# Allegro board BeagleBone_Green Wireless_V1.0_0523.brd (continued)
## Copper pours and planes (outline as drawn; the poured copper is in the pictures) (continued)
DGND on BOTTOM: 24.13,97.21 27.79,97.21 28.14,96.85 28.14,95.05 27.89,94.79 27.89,93.09 27.38,92.58 24.59,92.58 23.99,93.18 23.99,95.08 23.47,95.61 23.47,96.55
DGND on BOTTOM: 7.39,111.86 4.6,111.86 4.45,112.01 4.45,112.7 5.28,113.54 5.28,114.88 5.54,115.14 7.16,115.14 7.57,114.73 7.57,112.04
DGND on BOTTOM: 60.35,111.35 63.58,111.35 63.7,111.23 63.7,110.11 62.56,108.97 62.56,108.69 62.59,108.66 62.59,108.64 62.43,108.48 61.7,108.48 61.59,108.59 61.59,108.97 60.1,110.46 60.1,111.1
DGND on BOTTOM: 8.92,95.94 10.29,95.94 10.92,95.3 14.86,95.3 15.19,94.97 15.19,93.55 14.76,93.12 9.02,93.12 8.41,93.73 8.41,95.43
DGND on BOTTOM: 43.33,95.71 43.56,95.48 43.56,94.84 43.31,94.59 43.31,94.21 42.67,94.21 42.67,94.26 42.52,94.41 42.52,94.46 42.29,94.69 42.29,94.72 42.09,94.92 41.68,94.92 41.66,94.95 41.66,95.48 41.91,95.73 41.91,96.39 42.09,96.57 42.09,96.93 42.19,97.03 42.62,97.03 42.72,97.13 42.72,97.89 42.77,97.94 43.21,97.94 43.33,97.82
DGND on BOTTOM: 20.95,81.19 20.95,80.87 21.29,80.54 22.05,80.54 22.35,80.24 22.35,78.51 22.48,78.38 22.48,78.33 23.94,78.33 24.51,78.91 25.53,78.91 25.78,79.16 25.78,79.79 26.54,79.79 26.54,79.54 26.8,79.29 27.43,79.29 27.69,79.54 27.69,81.71 27.66,81.74 27.66,81.79 27.18,82.27 27.18,82.91 27.05,83.03 26.67,83.03 26.16,82.52 26.16,82.02 26.04,81.89 24.87,81.89 24.64,81.66 24.64,80.94 23.88,80.94 23.88,81.66 23.67,81.86 22.86,81.86 22.73,81.74 22.73,80.94 21.97,80.94 21.97,81.58 21.77,81.79 21.03,81.79 20.95,81.71 20.95,81.56 20.96,81.55 20.96,81.2
DGND on BOTTOM: 10.34,109.63 11.07,109.63 11.35,109.35 11.89,109.35 12.37,109.83 12.37,110.26 13.03,110.92 13.06,110.92 13.21,111.07 13.21,111.91 13.31,112.01 14.33,112.01 15.34,111 15.34,107.82 14.66,107.14 10.49,107.14 10.34,107.29
DGND on BOTTOM: 9.09,82.02 8.97,81.89 8.43,81.89 8.28,82.04 7.95,82.04 7.7,82.3 7.7,83.69 7.85,83.85 8.66,83.85 9.09,83.41
DGND on BOTTOM: 8.33,92.3 16.1,92.3 16.87,91.54 16.87,85.14 15.82,84.1 14.1,84.1 13.74,84.46 13.74,86.89 14.02,87.17 14.02,89.03 13.64,89.41 10.06,89.41 10.01,89.36 8.31,89.36 7.67,89.99 7.67,91.64
DGND on BOTTOM: outline of 210 points within 53.09,73.41 87.07,118.21
DGND on BOTTOM: 21.29,105.97 20.22,105.97 20.12,106.07 20.12,108.46 20.14,108.48 19.41,109.22 19.41,109.98 19.81,110.39 22.99,110.39 24.03,109.35 24.03,105.94 23.42,105.33 23.42,104.9 22.4,103.89 22.4,98.91 20.9,97.41 19.86,97.41 19.41,97.87 19.41,100.71 19.58,100.89 21.31,100.89 21.44,101.02 21.44,101.63 21.01,102.06 21.01,102.36 21.13,102.49 21.84,102.49 21.89,102.54 21.89,104.5 22.61,105.21 22.61,106.81 22.38,107.04 21.59,107.04 21.34,106.78 21.34,106.02
DGND on BOTTOM: 2.87,105.74 9.8,105.74 10.52,105.03 10.52,103.45 8.71,101.65 5.77,101.65 4.55,100.43 4.55,84.3 4.29,84.05 4.29,83.59 4.32,83.57 4.32,78.61 4.9,78.03 7.01,78.03 7.14,77.9 7.14,77.55 6.96,77.37 4.14,77.37 4.11,77.39 3.51,77.39 3.1,76.99 3.1,74.22 3.68,73.63 4.34,73.63 4.39,73.69 8.25,73.69 8.79,74.22 8.79,77.06 9.02,77.29 9.88,77.29 10.97,76.2 15.24,76.2 16.08,75.36 16.08,73.13 16.15,73.05 16.15,71.73 15.14,70.71 4.17,70.71 2.54,72.34 2.54,105.41
DGND on BOTTOM: 32.26,95.81 34.67,95.81 35.56,94.92 35.99,94.92 36.12,94.79 36.12,94.26 35.86,94.01 33.43,94.01 32.97,93.55 32.97,91.03 32.74,90.81 31.7,90.81 31.29,91.21 31.29,94.84
DGND on LYR2_GND: 87.12,77.83 83.59,69.29 75.06,65.76 7.75,65.76 3.71,67.43 2.03,71.48 2.03,113.39 3.71,117.43 7.75,119.1 75.06,119.1 75.22,119.1 75.39,119.1 78.13,118.62 81.36,117.3 81.92,116.71 81.92,116.43 85.69,112.66 87.1,107.52 87.12,107.16
DGND on LYR3: 78.82,103.63 75.34,107.11 74.4,107.11 72.82,108.69 72.82,116.36 74.55,118.08 81.28,118.08 85.6,113.77 85.6,112.9 85.98,112.52 85.98,109.98 85.73,109.73 85.14,109.73 83.13,107.72 83.13,105.38 81.38,103.63 ; 1 cut-out
DGND on LYR3: 46.52,101.82 46.74,101.6 47.24,101.6 47.37,101.73 47.37,106.27 46.86,106.78 46.86,108.92 46.2,109.58 45.39,109.58 45.06,109.25 45.06,106.53 46.38,105.21 46.38,104.04 45.82,103.48 45.82,102.29 46.29,101.82
DGND on LYR3: 68.07,100.99 71.6,97.46 71.6,85.83 70.59,84.81 70.59,83.54 70.36,83.31 69.75,83.31 69.55,83.52 69.29,83.52 69.04,83.26 69.04,81.61 68,80.57 56.97,80.57 56.39,81.15 56.39,81.99 56.52,82.12 57,82.12 57.61,81.51 57.61,81.41 57.96,81.05 66.17,81.05 67.95,82.83 67.95,95.35 63.55,99.75 57.96,99.75 57.61,100.1 57.61,100.33 57.81,100.53 58.39,100.53 58.85,100.99
DGND on LYR3: 3.53,105.64 16.23,105.64 17.07,104.8 17.07,103.12 15.9,101.96 11.58,101.96 10.79,101.17 10.79,95.61 11.76,94.64 15.42,94.64 16.66,93.4 16.66,88.44 17.4,87.71 17.4,84.58 16.28,83.46 11.48,83.46 10.93,82.92 10.93,77.3 11.43,76.81 15.72,76.81 16.15,76.38 16.15,74.78 15.85,74.47 13.31,74.47 12.56,73.72 12.56,71.23 12.14,70.82 4.67,70.82 3,72.49 3,105.08 3.53,105.61
DGND on LYR3: 26.42,84.68 27.81,83.29 27.81,82.91 28.83,81.89 28.83,80.37 27.1,78.64 27.1,77.22 25.91,76.02 25.4,76.02 25.15,76.28 25.15,76.5 24.38,77.27 24,77.27 23.94,77.2 22.59,77.2 19.25,80.54 19.25,82.5 19.79,83.03 22.86,83.03 23.88,84.05 23.88,84.18 24.38,84.68
DGND on LYR4: 77.42,103.78 72.39,108.81 69.19,108.81 68.58,108.2 62.99,108.2 61.52,109.68 61.52,111.63 58.83,114.33 58.83,116.84 59.05,117.07 77.6,117.07 78.49,117.96 79.81,117.96 81.23,117.27 82.37,116.54 85.12,113.51 85.93,112.19 85.93,109.98 83.36,107.42 83.36,105.36 81.79,103.78
DGND on LYR5_PWR: 32.26,73 39.62,73 40.77,71.86 40.77,69.95 41.02,69.7 61.98,69.7 62.61,70.33 62.61,80.85 62.94,81.18 67.61,81.18 68.94,82.5 68.94,83.06 69.44,83.57 69.44,95.96 68.45,96.95 68.25,96.95 64.77,100.43 61.47,100.43 61.01,99.97 56.46,99.97 55.96,100.48 55.96,105.59 55.42,106.12 54.84,106.12 52.6,108.36 51.31,108.36 49.38,110.29 48.36,110.29 48.01,110.64 48.01,118.14 48.44,118.57 77.72,118.57 77.72,118.21 78.49,117.45 78.74,117.45 78.8,117.51 80.45,117.51 85.6,112.37 85.6,109.22 85.57,109.19 85.57,104.19 85.29,103.91 85.29,93.65 86,92.94 86,85.95 85.62,85.57 85.62,76.56 84.1,75.03 79.83,75.03 78.44,73.63 78.44,67.87 76.96,66.4 25.27,66.4 24.89,66.78 24.89,70.33 25.91,71.35 30.61,71.35
GND_EARTH on TOP: 80.9,74.85 81.74,74.85 86.56,79.68 86.56,94.92 85.67,95.81 85.67,102.24 86.03,102.59 86.72,102.59 87.05,102.26 87.05,76.78 86.82,76.56 86.82,75.46 86.74,75.39 82.76,68.55 75.34,65.84 75.29,65.79 7.77,65.79 3.78,67.38 2.06,71.32 2.06,113.51 4.11,117.64 8.48,119.08 18.8,119.08 19.15,118.72 19.15,115.87 17.68,114.4 13.72,114.4 12.37,115.75 8.61,115.75 7.87,116.48 4.93,116.48 4.83,116.38 4.83,113.39 3.38,111.94 3.38,109.27 3.53,109.12 3.89,109.12 4.85,108.15 4.85,106.27 4.62,106.05 3.58,106.05 2.63,105.09 2.63,71.77 4.19,70.21 15.39,70.21 15.75,70.56 21.87,70.56 22.53,69.9 22.53,67.01 23.29,66.24 29.64,66.24 30.05,66.65 69.72,66.65 72.57,69.49 72.57,70.48 72.76,70.68 77.43,70.68 78.97,72.21 78.97,72.92
GND_EARTH on BOTTOM: 79.3,74.85 81.74,74.85 86.56,79.68 86.56,79.71 86.59,79.68 87.05,79.68 87.05,76.78 86.82,76.56 86.82,75.46 86.74,75.39 82.76,68.55 75.34,65.84 75.29,65.79 7.77,65.79 3.78,67.38 2.06,71.32 2.06,113.51 4.11,117.64 8.48,119.08 18.8,119.08 19.15,118.72 19.15,115.87 17.68,114.4 13.72,114.4 12.37,115.75 8.1,115.75 7.04,114.68 7.04,113.54 6.73,113.23 4.67,113.23 4.32,112.88 4.32,108.94 5.03,108.23 6.55,108.23 6.73,108.05 6.73,106.38 6.4,106.05 2.74,106.05 2.34,105.64 2.34,72.06 4.19,70.21 15.39,70.21 17.27,72.09 18.52,72.09 20.04,70.56 21.87,70.56 22.53,69.9 22.53,67.01 23.29,66.24 26.67,66.24 26.82,66.09 30.05,66.09 30.61,66.65 69.72,66.65 72.57,69.49 72.57,70.48 73.03,70.94 77.29,70.94 78.41,72.06 78.41,73.96
GND_EARTH on LYR3: 79.3,74.85 81.74,74.85 86.56,79.68 86.56,93.9 86.5,93.97 86.5,95.71 85.78,96.43 85.78,105.41 86.18,105.82 86.18,107.16 86.13,107.21 86.13,109.3 86.26,109.42 86.54,109.42 86.82,109.14 86.82,107.31 87.1,107.04 87.1,94.89 87.05,94.84 87.05,76.78 86.82,76.56 86.82,75.46 86.74,75.39 82.76,68.55 75.34,65.84 75.29,65.79 7.77,65.79 3.78,67.38 2.06,71.32 2.06,113.51 4.11,117.64 8.48,119.08 18.8,119.08 19.15,118.72 19.15,115.87 17.68,114.4 13.72,114.4 12.37,115.75 8.1,115.75 8.09,115.74 5.88,115.74 5.18,115.04 5.18,113.74 4.32,112.88 4.32,108.94 5.03,108.23 5.08,108.23 5.05,108.2 5.05,106.48 4.62,106.05 2.74,106.05 2.34,105.64 2.34,72.06 4.19,70.21 15.39,70.21 16.14,70.95 18.1,70.95 19.23,69.82 19.23,67.26 20.24,66.24 29.64,66.24 30.05,66.65 69.72,66.65 72.57,69.49 72.57,70.48 73.03,70.94 77.29,70.94 78.41,72.06 78.41,73.96
GND_EARTH on LYR4: 79.3,74.85 81.74,74.85 86.56,79.68 86.56,95.45 86.22,95.8 86.09,95.8 85.57,96.32 85.57,100.23 85.93,100.58 85.93,109.12 86.13,109.32 86.54,109.32 86.79,109.07 86.79,107.98 87.05,107.72 87.05,76.78 86.82,76.56 86.82,75.46 86.74,75.39 82.76,68.55 75.34,65.84 75.29,65.79 7.77,65.79 3.78,67.38 2.06,71.32 2.06,113.51 4.11,117.64 8.48,119.08 18.8,119.08 19.15,118.72 19.15,115.87 17.68,114.4 13.72,114.4 12.37,115.75 8.1,115.75 7.04,114.68 7.04,113.54 6.73,113.23 4.67,113.23 4.32,112.88 4.32,107.11 3.76,106.55 3.76,106.35 2.79,105.38 2.79,72.82 5.41,70.21 15.39,70.21 15.77,70.59 17.14,70.59 19.81,67.92 20.93,67.92 21.59,67.26 22.53,67.26 22.53,67.01 23.29,66.24 29.64,66.24 30.05,66.65 69.72,66.65 72.57,69.49 72.57,70.48 73.03,70.94 77.29,70.94 78.41,72.06 78.41,73.96
GND_OSC0 on BOTTOM: 39.42,103.91 39.22,104.11 36.02,104.11 35.89,104.24 35.89,110.24 35.81,110.31 35.99,110.49 41.2,110.49 41.68,110.01 41.68,109.93 42.8,108.81 43.08,108.81 43.1,108.79 44.04,108.79 44.45,109.19 46.43,109.19 47.6,108.03 47.6,105.51 46.23,104.14 44.55,104.14 43.9,104.79 43.9,105.42 43.71,105.61 41.78,105.61 41.2,105.03 40.69,105.03 40.46,104.8 40.46,104.42 39.95,103.91 ; 1 cut-out
GND_OSC1 on TOP: 49.66,75.29 49.91,75.03 55.12,75.03 55.37,75.29 55.37,82.91 54.48,83.79 53.72,83.79 52.45,85.06 52.45,86.97 51.56,87.86 50.29,87.86 50.16,87.73 50.16,85.32 49.53,84.68 49.53,83.79 49.66,83.67
VDD_1V8 on TOP: 26.07,84.47 25.6,84.94 25.6,85.09 26.57,86.06 27.64,86.06 28.17,86.59 28.17,87.73 28.3,87.86 28.5,87.86 28.52,87.83 28.68,87.99 29.11,87.99 30.28,89.15 30.81,89.15 30.84,89.18 31.11,89.18 31.34,88.95 31.34,88.42 29.9,86.97 29.9,85.67 29.08,84.86 26.92,84.86 26.53,84.47
VDD_1V8 on BOTTOM: 38.48,98.86 38.53,98.91 38.53,98.96 38.81,99.24 39.19,99.24 39.37,99.06 39.37,98.4 39.8,97.97 41.58,97.97 41.81,97.74 41.81,97.54 41.55,97.28 40.46,97.28 40.41,97.33 37.46,97.33 37.26,97.13 36.17,97.13 35.81,96.77 35.81,95.89 35.71,95.78 34.98,95.78 34.51,96.25 34.51,96.84 34.49,96.85 34.49,97.82 34.82,98.15 35.51,98.15 36.22,98.86
VDD_1V8 on LYR3: 41.68,97.38 37.54,97.38 37.39,97.54 37.39,98.5 37.77,98.88 38.2,98.88 38.73,99.42 40.08,99.42 40.34,99.67 41.4,99.67 41.81,99.26 41.81,97.51
VDD_1V8 on LYR4: 31.29,88.19 31.7,88.6 31.7,90.53 33.2,92.02 34.09,92.02 34.52,92.46 34.52,93.85 36.27,95.61 36.27,96.98 36.08,97.17 34.73,97.17 34.57,97 34.57,95.07 33.2,93.7 31.37,93.7 30.63,92.96 30.63,90.65 30.05,90.07 30.05,88.34 30.2,88.19
VDD_1V8 on LYR4: 47.12,90.27 46.86,90.02 43.05,90.02 42.8,90.27 42.8,93.57 42.55,93.83 41.4,93.83 41.15,94.08 41.15,99.42 41.4,99.67 43.94,99.67 44.2,99.92 44.2,100.38 44.58,100.76 46.53,100.76 47.12,100.18 47.12,94.84 46.74,94.46 46.74,94.21 47.12,93.83
VDD_1V8 on LYR5_PWR: 46.1,79.1 46.1,90.4 46.23,90.53 48.13,90.53 48.26,90.4 48.26,85.57 48.64,85.19 50.29,85.19 50.55,84.94 50.55,79.1 50.29,78.84 46.35,78.84
VDD_1V8_WIFI on BOTTOM: 73,88.6 74.37,88.6 74.7,88.93 74.7,89.64 74.68,89.66 74.68,90.09 74.19,90.58 74.19,97.92 73.41,98.7 72.31,98.7 71.65,99.36 71.65,101.6 72.54,102.49 72.54,103.33 72.31,103.56 70.51,103.56 70.23,103.28 70.23,102.57 70.59,102.21 70.71,102.21 70.97,101.96 70.97,101.19 70.61,100.84 70.61,99.31 72.54,97.38 72.54,95.91 72.8,95.66 72.8,88.8
VDD_3V3_WIFI on TOP: 63.04,113.87 64.06,113.87 64.24,113.69 64.24,112.19 64.08,112.04 63.07,112.04 62.99,112.12 62.99,113.61 62.92,113.69 62.92,113.74
VDD_3V3_WIFI on BOTTOM: 56.77,108.94 56.9,109.07 56.9,110.03 59.06,112.2 59.06,113.73 59.25,113.92 64.24,113.92 64.44,113.72 64.44,113.08 63.25,111.89 60.22,111.89 59.49,111.15 59.49,110.34 60.02,109.8 60.58,109.8 60.99,109.4 60.99,108.86 60.39,108.27 54.9,108.27 54.05,107.42 53.7,107.42 53.44,107.67 53.44,108.15 54.23,108.94
VDD_3V3_WIFI on LYR4: 57.81,110.46 60.32,110.46 61.19,109.6 61.19,109.09 60.66,108.56 60.35,108.56 60.22,108.43 60.22,107.57 61.09,106.71 62.61,106.71 63.37,105.94 63.37,105.41 62.51,104.55 61.29,104.55 57.58,108.25 57.58,110.24
VDD_3V3A on BOTTOM: 39.98,96.39 41.63,96.39 41.81,96.57 41.81,96.93 42.04,97.16 42.44,97.16 42.57,97.28 42.57,97.66 42.42,97.82 42.19,97.82 41.76,97.38 41.76,97.31 41.63,97.18 41.48,97.18 41.4,97.1 39.98,97.1 39.85,96.98 39.85,96.52
VDD_3V3A on BOTTOM: 42.16,94.36 42.16,94.21 42.42,93.95 43.05,93.95 43.31,93.7 43.31,92.68 42.8,92.68 42.8,93.07 42.42,93.45 41.91,93.45 41.66,93.7 40.49,93.7 40.11,94.08 40.11,95.07 40.18,95.15 41.17,95.15 41.25,95.07 41.25,94.77 41.45,94.56 41.96,94.56
VDD_3V3A on BOTTOM: 43.69,101.57 43.69,100.94 43.31,100.56 43.31,98.4 43.56,98.15 44.7,98.15 44.83,98.27 44.83,98.4 44.45,98.78 44.45,100.69 44.16,100.98 44.16,101.57
VDD_3V3A on BOTTOM: 49.53,98.15 51.43,98.15 51.69,98.4 51.69,100.3 52.15,100.77 52.15,101.57 51.95,101.78 50.04,101.78 49.89,101.63 49.89,100.79 49.66,100.56 49.66,98.78 49.4,98.53 49.4,98.27
VDD_3V3A on LYR5_PWR: 22.99,76.81 22.73,77.06 22.73,89.13 24.51,90.91 25.27,90.91 29.84,95.48 29.84,102.34 30.86,103.35 34.8,103.35 35.86,104.42 35.86,110.06 36.22,110.41 42.27,110.41 42.85,109.83 49.35,109.83 51.23,107.95 52.53,107.95 54.58,105.89 55.07,105.89 55.65,105.31 55.65,100.36 55.24,99.95 55.24,99.92 54.99,99.67 51.94,99.67 51.56,99.29 51.56,96.62 50.55,95.61 50.55,94.59 50.29,94.34 43.94,94.34 43.43,93.83 43.43,93.45 43.31,93.32 42.04,93.32 41.78,93.07 41.78,92.43 42.04,92.18 43.31,92.18 43.56,91.92 43.56,91.67 42.55,90.65 42.55,90.02 42.8,89.76 44.2,89.76 44.45,90.02 44.45,90.4 44.58,90.53 45.72,90.53 45.85,90.4 45.85,78.97 46.23,78.59 50.29,78.59 50.55,78.33 50.55,70.71 50.29,70.46 41.27,70.46 41.02,70.71 41.02,76.43 40.64,76.81
VDD_3V3B on BOTTOM: 19.43,107.29 17.37,107.29 17.25,107.16 17.25,104.22 17.48,103.99 20.7,103.99 21.21,104.5 21.21,105.38 20.83,105.77 19.68,105.77 19.56,105.89 19.56,107.16
VDD_3V3B on BOTTOM: 58.6,111.89 57.68,111.89 57.15,112.42 57.15,114.05 57.48,114.38 58.42,114.38 58.7,114.1 58.7,111.99
VDD_3V3B on LYR5_PWR: 20.13,66.4 19.49,67.03 19.49,69.57 17.91,71.16 14.1,71.16 11.56,68.62 5.21,68.62 3.3,70.52 3.3,113.39 4.6,116.53 7.75,117.83 12.19,117.83 12.51,117.51 12.51,115.29 14.1,113.7 17.91,113.7 19.49,115.29 19.49,117.83 20.13,118.47 60.48,118.47 85.65,93.29 85.65,82.25 84.33,80.92 77.6,80.92 75.74,82.78 75.74,94.11 59.77,110.08 43.1,110.08 42.52,110.67 36.09,110.67 35.64,110.21 35.64,104.57 34.8,103.73 30.73,103.73 29.46,102.46 29.46,95.73 25.02,91.29 24.13,91.29 22.48,89.64 22.48,76.94 22.86,76.56 40.45,76.56 40.77,76.24 40.77,70.84 40.45,70.52 27.43,70.52 27.11,70.21 27.11,66.71 26.8,66.4
VDD_5V on TOP: 20.66,78.86 20.66,79.07 18.67,79.07 17.98,78.38 17.98,76.84 18.14,76.68 19.07,76.68 19.75,77.37 19.75,78.11 20.51,78.86
VDD_5V on BOTTOM: 18.06,78.77 19.13,78.77 19.33,78.56 20.17,78.56 20.7,78.03 20.7,77.17 20.22,76.68 18.16,76.68 17.91,76.94 17.91,77.42 17.93,77.44 17.93,78.64
VDD_5V on LYR4: 19.71,78.46 20.09,78.08 20.09,73.94 20.69,73.34 22.9,73.34 24.43,71.81 25.96,71.81 27.14,70.62 27.14,66.51 27.05,66.42 25.37,66.42 24.59,67.21 24.59,67.23 24.16,67.23 23.14,68.25 20.73,68.25 20.6,68.38 20.57,68.38 16.97,71.98 16.97,77.88 17.55,78.46
VDD_CORE on TOP: 28.7,79.22 28.7,78.08 28.96,77.83 32.03,77.83 32.04,77.84 33.19,77.84 33.5,78.16 33.5,84.15 33.1,84.56 33.1,85.92 34.47,87.29 34.47,88.27 34.44,88.29 34.44,88.49 37.33,91.38 37.33,93.14 35.81,94.65 34.25,94.65 33.81,94.21 33.81,91.49 31.61,89.29 31.61,88.56 30.23,87.17 30.23,83.34 31.09,82.47 31.09,80.59 30.48,79.98 28,79.98 27.88,79.87 27.3,79.87 27.3,79.67 28.26,79.67
VDD_CORE on BOTTOM: 37.29,92.74 37.29,90.53 35.89,89.13 34.29,89.13 33.78,89.64 33.4,89.64 33.27,89.76 33.27,93.45 33.53,93.7 35.79,93.7 36.55,92.94 37.08,92.94
VDD_CORE on LYR3: 50.55,90.65 47.37,90.65 47.12,90.91 47.12,92.05 46.74,92.43 43.81,92.43 43.56,92.18 43.56,89.26 43.31,89 34.16,89 33.4,89.76 33.4,93.12 36.68,96.39 40.46,96.39 40.69,96.62 42.8,96.62 43.18,97 44.83,97 46.61,98.78 50.55,98.78 50.8,98.53 50.8,90.91
VDD_CORE on LYR4: 33.15,91.41 34.52,91.41 34.87,91.06 34.87,89.38 34.01,88.52 34.01,86.49 33.25,85.73 33.25,78.59 32.79,78.13 31.37,78.13 30.71,78.79 30.71,83.44 30.28,83.87 30.28,86.69 32.11,88.52 32.11,90.37
VDD_MPU on TOP: 26.61,76.87 26.42,76.87 26.42,77.51 27.11,77.51 27.94,76.68 30.23,76.68 30.86,76.05 30.86,73.25 30.48,72.87 29.34,72.87 29.08,73.13 29.08,74.27 28.57,74.78 27.74,74.78 27.3,75.21 27.3,76.17
VDD_MPU on TOP: 36.73,87.73 37.69,87.73 37.92,87.5 37.92,86.56 37.59,86.23 36.68,86.23 36.45,86.46 36.45,87.45
VDD_MPU on BOTTOM: 27.48,75.44 28.6,75.44 28.85,75.18 28.85,72.97 28.65,72.77 27.58,72.77 27.36,73 27.36,75.31
VDD_MPU on LYR3: 46.86,86.21 46.86,91.92 46.61,92.18 43.94,92.18 43.81,92.05 43.81,88.75 42.67,87.6 37.34,87.6 37.21,87.48 37.21,86.46 37.34,86.33 41.53,86.33 41.91,85.95 46.61,85.95
VDD_PLL on BOTTOM: 44.96,98.65 45.47,98.15 45.59,98.15 46.48,99.03 46.48,99.29 46.1,99.67 46.1,100.56 45.37,101.29 45.37,101.57 44.86,101.57 44.86,100.91 44.96,100.81
VDD_PLL on BOTTOM: 49.91,85.19 49.91,87.86 50.16,88.11 50.16,90.27 49.91,90.53 49.15,90.53 48.89,90.27 48.89,86.33 49.4,85.83 49.4,85.19
VDD_PLL on BOTTOM: 38,97.21 38.48,97.21 38.63,97.05 38.63,96.67 37.82,95.86 37.82,95.43 37.64,95.25 37.64,94.03 38.23,93.45 41.35,93.45 41.63,93.17 42.37,93.17 42.55,92.99 42.55,92.53 42.32,92.3 41.61,92.3 41.45,92.46 38.02,92.46 36.33,94.15 36.33,95.26 36.17,95.43 36.17,96.6 36.25,96.67 37.74,96.67 37.92,96.85 37.92,97.13
VDD_PLL on LYR5_PWR: 42.04,92.56 42.16,92.43 43.81,92.43 44.07,92.68 47.75,92.68 48.51,91.92 48.51,90.27 48.64,90.14 50.29,90.14 50.55,90.4 50.55,93.83 50.29,94.08 44.07,94.08 43.69,93.7 43.69,93.32 43.43,93.07 42.16,93.07 42.04,92.94
VDDS on BOTTOM: 49.28,100.62 49.66,101 49.66,101.7 49.53,101.83 48.21,101.83 47.93,102.11 47.93,102.64 47.78,102.79 47.12,102.79 46.94,102.62 46.94,102.24 46.99,102.18 47.24,102.18 47.5,101.93 47.5,100.89 48.13,100.25 48.13,99.03 47.75,98.65 47.75,98.27 47.88,98.15 48.64,98.15 49.28,98.78
VDDS on BOTTOM: 40,87.73 40.77,87.73 41.02,87.99 41.02,88.75 41.27,89 42.67,89 42.93,89.26 42.93,89.64 43.05,89.76 43.31,89.76 43.43,89.89 43.43,90.53 43.31,90.65 42.67,90.65 41.91,91.41 41.02,91.41 40.77,91.16 40.77,90.4 40.51,90.14 39.88,90.14 39.88,87.86
VDDS on LYR4: 47.62,90.78 47.37,91.03 47.37,93.95 47.12,94.21 47.12,94.46 47.37,94.72 47.37,99.67 47.62,99.92 50.55,99.92 50.8,99.67 50.8,89.38 50.55,89.13 49.4,89.13 49.15,89.38 49.15,90.53 48.89,90.78
VDDS on LYR5_PWR: 44.07,90.02 42.93,90.02 42.8,90.14 42.8,90.53 43.81,91.54 43.81,92.05 44.2,92.43 47.62,92.43 48.26,91.8 48.26,90.91 48.13,90.78 44.45,90.78 44.2,90.53 44.2,90.14
VDDS_DDR on TOP: 23.72,74.37 24.49,74.37 24.74,74.12 24.74,73 24.71,72.97 24.71,72.72 24.97,72.47 24.97,72.31 24.74,72.09 23.83,72.09 23.6,72.31 23.6,74.24
VDDS_DDR on BOTTOM: 19.86,73.61 20.52,73.61 20.68,73.46 20.68,72.69 20.88,72.49 21.46,72.49 22.12,71.83 23.32,71.83 23.55,72.06 23.55,72.39 23.7,72.54 24.94,72.54 25.12,72.36 25.12,71.25 24.69,70.82 20.55,70.82 19.71,71.65 19.71,73.46
VDDS_DDR on LYR3: 61.72,68.2 61.57,68.05 20.17,68.05 19.81,68.4 19.81,73.51 20.07,73.76 28.57,73.76 29.87,72.47 61.14,72.47 61.72,71.88
VDDS_DDR on LYR5_PWR: 50.8,95.48 50.8,90.4 51.05,90.14 51.43,90.14 51.69,89.89 51.69,85.83 50.8,84.94 50.8,71.09 51.05,70.84 61.72,70.84 62.04,71.16 62.04,81 62.36,81.32 66.32,81.32 66.59,81.58 67.49,81.58 68.68,82.78 68.68,83.29 69.11,83.72 69.11,95.81 68.33,96.6 68.05,96.6 64.59,100.05 61.72,100.05 61.4,99.73 55.44,99.73 55.12,99.42 52.07,99.42 51.82,99.16 51.82,96.49
HUB_AVDD on TOP: 30.38,92.33 31.19,92.33 31.39,92.13 31.39,91.31 29.82,89.74 29.82,89.1 29.36,88.65 28.3,88.65 28.14,88.8 28.14,89.94 28.3,90.09 28.3,90.83 28.27,90.86 28.27,91.16 28.47,91.36 29.39,91.36 29.41,91.34 30.02,91.34 30.38,91.69
HUB_AVDD on BOTTOM: 29.84,97.46 29.84,93.19 30.7,92.34 30.7,90.82 30.4,90.53 29.06,90.53 28.22,91.36 28.22,94.72 28.35,94.84 28.35,97.16 28.07,97.43 23.93,97.43 23.22,96.72 23.22,95.43 23.7,94.95 23.7,92.51 22.89,91.69 20.47,91.69 20.32,91.85 20.32,92.94 20.57,93.19 22.17,93.19 22.63,93.65 22.63,94.92 21.79,95.76 21.79,97.56 23.37,99.14 26.29,99.14 27.05,98.37 28.93,98.37
HUB_VBUS on BOTTOM: 7.9,81.71 8.25,81.71 8.69,81.28 8.69,80.26 8.23,79.81 6.27,79.81 5.77,79.3 5.77,78.44 5.64,78.31 5.03,78.31 4.57,78.77 4.57,83.74 4.9,84.07 4.9,99.87 5.31,100.28 6.73,100.28 6.73,100.1 6.91,99.92 6.91,99.47 7.49,98.88 7.49,97.71 6.97,97.19 6.97,95.44 7.52,94.89 7.52,89.54 7.98,89.08 9.83,89.08 10.54,88.37 10.54,87.66 10.34,87.45 8.18,87.45 7.49,86.77 7.49,82.12
P_L1 on TOP: 24.58,76.18 24.58,75.86 24,75.29 23.62,75.29 23.49,75.16 23.49,74.9 23.75,74.65 24.89,74.65 25.15,74.9 25.15,76.24 24.89,76.49
P_L1 on BOTTOM: 23.29,75.44 24.51,75.44 24.79,75.16 24.79,72.92 24.64,72.77 23.42,72.77 23.16,73.03 23.16,75.31
P_L2 on TOP: 26.04,74.65 25.78,74.9 25.78,75.79 25.91,75.92 25.91,76.59 26.04,76.72 26.12,76.72 26.92,75.92 26.92,74.9 26.67,74.65
P_L2 on BOTTOM: 25.45,75.49 26.72,75.49 26.87,75.34 26.87,73.13 26.52,72.77 25.37,72.77 25.15,73 25.15,75.18
P_L3 on TOP: 27.84,80.47 27.3,80.47 27.3,80.68 28.13,80.68 28.7,81.25 28.7,81.97 29.01,82.27 30.76,82.27 30.76,80.98 30.4,80.62 29.21,80.62 28.96,80.37 27.94,80.37
SYS_5V on TOP: 28.96,100.56 30.28,100.56 30.56,100.28 30.56,99.14 30.12,98.7 28.55,98.7 28.5,98.76 28.5,99.64 28.78,99.92 28.78,100.38
SYS_5V on BOTTOM: 72.92,77.34 72.92,74.07 72.89,74.03 72.9,74.02 72.9,73.38 72.52,73 72.52,72.95 70.54,70.97 70.54,68.61 69.6,67.67 30.56,67.67 30.12,67.23 30.12,66.68 29.62,66.17 27.46,66.17 27.35,66.27 27.35,66.39 27.05,66.69 27.05,70.71 27.76,71.42 28.22,71.42 29.34,72.54 29.34,75.01 28.5,75.84 24.94,75.84 24.28,76.5 24.28,77.93 24.51,78.16 27.86,78.16 28.02,78 28.02,77.98 27.97,77.93 27.97,77.27 28.35,76.89 29.64,76.89 31.19,75.34 31.19,72.92 32.36,71.76 45.39,71.76 45.49,71.86 57.43,71.86 58.29,72.72 68.05,72.72 69.52,74.19 69.52,78.49 71.17,80.14 71.17,80.16 71.5,80.49 73.03,80.49 73.28,80.75 76.15,80.75 76.3,80.59 76.3,78.26 76.15,78.11 76.15,78.08 73.66,78.08
SYS_5V on BOTTOM: 24.56,100.51 25.48,100.51 25.78,100.81 25.78,102.97 25.65,103.1 23.75,103.1 23.62,102.97 23.62,102.59 23.49,102.46 22.81,102.46 22.61,102.26 22.61,100.94 22.99,100.56 24.51,100.56
SYS_5V on LYR3: 21.84,101.8 25.02,101.8 27.15,99.67 28.47,99.67 28.75,99.95 29.03,99.95 29.34,99.64 29.34,98.32 29.21,98.2 26.47,98.2 24.07,100.6 21.78,100.6 21.56,100.81 20.8,100.81 20.12,101.5 20.12,102.29 20.27,102.44 21.21,102.44
SYS_5V on LYR4: 27.91,100.05 29.16,100.05 29.59,99.62 29.59,92.05 28.07,90.53 28.07,86.18 28.03,86.14 28.03,85.28 26.67,83.92 26.67,82.19 26.9,81.97 26.9,78.16 30.76,74.3 30.76,68.76 29.49,67.49 29.49,66.83 29.16,66.5 28.3,66.5 27.53,67.26 27.57,67.3 27.57,70.83 24.74,73.66 24.74,76.12 23.44,77.42 22.02,77.42 19.89,79.55 19.89,81.2 19.41,81.69 19.41,83.16 21.92,85.67 25.43,85.67 26.24,86.49 26.24,91.01 27.23,92 27.23,93.6 27.51,93.88 27.51,99.64
USB_DC on TOP: 20.83,78.28 21.51,78.28 21.59,78.21 21.59,77.95 21.72,77.83 21.72,76.05 21.34,75.67 21.29,75.67 21.03,75.41 21.03,74.63 21.44,74.22 21.44,72.03 20.75,71.35 17.75,71.35 16.46,72.64 16.46,73.33 15.82,73.96 10.26,73.96 10.19,74.04 9.37,74.04 9.27,74.14 7.62,74.14 7.37,73.89 3.91,73.89 3.58,74.22 3.58,76.71 4,77.13 8.57,77.13 8.86,77.42 10.39,77.42 10.59,77.22 15.62,77.22 17.83,75.01 19.25,75.01 19.79,75.54 19.79,76.56 20.37,77.14 20.37,77.83
USB_DC on BOTTOM: 5.49,109.7 8.36,109.7 8.94,109.12 9.78,109.12 10.03,108.86 10.03,107.29 9.78,107.04 7.87,107.04 7.37,107.54 7.37,107.92 7.11,108.18 7.11,108.25 6.3,109.07 6.3,109.12 6.25,109.12 6.1,109.27 5.51,109.27 5.41,109.37 5.41,109.63
USB_DC on BOTTOM: 5.74,77.06 5.82,76.99 5.82,76.25 6.53,75.54 6.65,75.54 6.96,75.23 6.96,74.12 6.83,73.99 6.1,73.99 5.84,74.24 4.24,74.24 4.01,74.02 3.78,74.02 3.56,74.24 3.56,76.66 3.96,77.06
USB_DC on BOTTOM: 20.57,75.67 20.37,75.87 20.37,76.68 20.45,76.76 20.85,76.76 21.11,77.01 21.11,78.26 21.31,78.46 21.97,78.46 22.35,78.08 22.35,76.68 22.22,76.56 22.22,76.05 21.84,75.67
USB_DC on LYR4: 6.86,109.47 8.97,109.47 9.53,108.92 9.53,106.63 8.74,105.84 7.98,105.84 7.04,104.9 7.04,87.38 6.88,87.22 6.88,79.25 5.74,78.11 5.74,77.7 6.78,76.66 6.78,76.63 7.01,76.4 7.01,74.3 6.38,73.66 3.94,73.66 3.4,74.19 3.4,78.87 4.14,79.6 4.14,106.06 4.56,106.48 4.56,107.18
VDCDC1 on TOP: 21.91,75.86 23.62,75.86 24.36,76.59 24.36,77.31 24.56,77.31 24.56,76.41 24.38,76.24 24.38,75.92 23.88,75.41 23.24,75.41 22.99,75.16 22.99,74.9 22.73,74.65 21.46,74.65 21.21,74.9 21.21,75.29 21.72,75.79 21.84,75.79
VDCDC1 on BOTTOM: 22.61,75.13 22.61,73.05 22.38,72.82 21.34,72.82 21.16,73 21.16,73.53 20.75,73.94 19.99,73.94 19.81,74.12 19.81,74.88 20.35,75.41 22.33,75.41
VRTC on LYR3: 49.91,89.76 49.15,89.76 48.89,89.51 48.89,86.72 48.51,86.33 48.51,85.95 48.64,85.83 50.67,85.83 50.8,85.95 50.8,86.33 50.16,86.97 50.16,89.51
VRTC on LYR5_PWR: 48.77,85.45 50.93,85.45 51.43,85.95 51.43,89.76 51.31,89.89 48.64,89.89 48.51,89.76 48.51,85.7
N22732977 on BOTTOM: 75.84,84.1 76.15,84.1 76.23,84.02 76.23,81.76 75.72,81.25 73.41,81.25 73.28,81.38 73.28,83.31 74.04,84.07 74.5,84.07 74.57,84 74.57,83.29 74.63,83.24 74.7,83.24 74.8,83.34 74.8,84 74.88,84.07 75.01,84.07 75.08,84 75.08,83.26 75.21,83.13 75.74,83.13 75.77,83.16 75.77,84.02
N22733304 on BOTTOM: 73.03,88.01 74.55,88.01 74.98,87.58 74.98,86.72 75.13,86.56 75.18,86.56 75.18,85.22 75.06,85.09 74.85,85.09 74.8,85.14 74.8,85.8 74.42,86.18 73.18,86.18 72.9,86.46 72.9,87.88
N22764895 on TOP: 27.05,92.99 27.71,92.99 27.99,92.71 27.99,90.7 27.79,90.5 26.9,90.5 26.82,90.58 26.82,91.29 26.97,91.44 26.97,92.91
N22765441 on TOP: 30.3,96.6 29.62,95.91 27.94,95.91 27.84,96.01 27.84,96.16 27.91,96.24 28.7,96.24 29.01,96.55 29.01,98.02 29.31,98.32 30.25,98.32 30.3,98.27
N22769591 on BOTTOM: 7.7,101.55 9.37,101.55 10.72,102.9 13.28,102.9 14.02,102.16 15.11,102.16 15.13,102.15 15.79,102.15 15.98,101.96 15.98,99.95 15.54,99.52 13.67,99.52 13.21,99.97 13.21,101.09 12.52,101.78 11.33,101.78 9.55,100 8.66,100 8.56,99.9 8.56,99.49 8.38,99.31 7.72,99.31 7.54,99.49 7.54,101.4
N22769632 on BOTTOM: 11.48,99.34 10.9,98.76 10.9,96.67 10.44,96.22 8.69,96.22 8.51,96.04 8.51,95.89 8.38,95.76 7.52,95.76 7.39,95.89 7.39,96.88 7.51,96.99 7.53,96.99 8.25,97.71 9.3,97.71 9.75,98.17 9.75,99.31 9.82,99.38 9.82,99.76 11.48,101.42 12.14,101.42 12.67,100.89 12.67,99.59 12.42,99.34
N22770199 on BOTTOM: 13.31,87 13.31,84.43 14.07,83.67 15.39,83.67 15.65,83.41 15.65,81.66 15.19,81.2 13.34,81.2 12.9,81.64 12.9,82.75 11.05,84.61 11.05,88.39 11.58,88.93 13.56,88.93 13.7,88.79 13.7,87.39
N22770224 on BOTTOM: 12.5,82.73 12.5,81.33 12.12,80.95 11.84,80.95 11.81,80.98 11.43,80.98 10.82,80.37 10.29,80.37 10.26,80.34 9.7,80.34 9.42,80.62 9.42,83.29 9.73,83.59 11.63,83.59
N22868125 on BOTTOM: 21.59,102.97 20.95,102.97 20.32,103.61 17.91,103.61 17.78,103.48 17.78,102.08 17.91,101.96 20.07,101.96 20.83,102.72 21.59,102.72

Small or netless copper shapes (teardrops, artwork), in the pictures only: 214 on TOP, 106 on BOTTOM, 61 on LYR3, 20 on LYR4

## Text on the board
Board Geometry/Soldermask Bottom: SMS
Ref Des/Silkscreen Bottom: microSD Card | USB | S/N | P8
Board Geometry/Outline: V_CUT | V1.0
TOP: BeagleBone Green | Wireless V1.0 | D
Board Geometry/Soldermask Top: BeagleBone Green | Wireless V1.0 | SMC
Ref Des/Silkscreen Top: PWR | PGANG | GND | NC | AM335x | RX | TX | USER | WLAN | BT | TXD | 3V3 | SDA | RXD | SCL | UART | I2C | RESET | POWER | ANT2 | ANT1 | USB1/2 | USB3/4 | (OZ) | LAYER 1 - PRIMARY SIDE - SIGNAL | LAYER 2 - GROUND PLANE | LAYER 3 - SIGNAL | LAYER 4 - SIGNAL | LAYER 5 - SPLIT POWER PLANE | LAYER 6 - SECONDARY SIDE - SIGNAL | LAYER# | COPPER WEIGHT | HALF+PLATING | IMPEDANCE CONTROL | +/- 10% | 50ohm SINGLE ENDED | TRACE WIDTH | TRACE WIDTH / SPACE | 90ohm DIFFERENTIAL | 100ohm DIFFERENTIAL | 1 | 5.25 | 4.75 | 4.5/6.5 | 5.0/7.0 | 3.75/7.25 | 4.00/8.00 | LAYER STACK-UP - ALL DIMENSIONS IN INCHES
DISPLAY_TOP: SPC
DISPLAY_BOTTOM: SPS
DIMENSION: R.250 2X
USER_PART_NUM_TOP: TSLKC
USER_PART_NUM_BOTTOM: BSLKC
User.13: C100 | C73 | C97 | C98 | C99 | C25 | C48 | C46 | C58 | C41 | C66 | C65 | C60 | C70 | C26 | C87 | C45 | C79 | C54 | C44 | C82 | C83 | R49 | C84 | C69 | R158 | C71 | C86 | C85 | C67 | C38 | C78 | C52 | C53 | C51 | R116 | R131 | R140 | R134 | R145 | R113 | R138 | R115 | R112 | R114 | R117 | C134 | R150 | R154 | R155 | R153 | C154 | R151 | R152 | C68 | C43 | C50 | C81 | C56 | C42 | C47 | R17 | C49 | C72 | C88 | C106 | C94 | C63 | C80 | FB1 | C40 | C39 | D2 | D3 | D4 | D5 | USER LEDS | 0 | 1 | 2 | 3 | D1 | RESET | C19 | R10 | R72 | R73 | R74 | R71 | POWER | R9 | R7 | U10 | C1 | TP5 | TP6 | C16 | C3 | R5 | TP7 | TP8 | TP9 | C9 | C12 | P | R119 | R118 | A | R139 | R133 | R128 | R127 | R126 | R125 | R124 | R28 | 14 | 18 | U3 | Y4 | R27 | TP3 | V | TP1 | C96 | 16 | TP2 | 64 | 17 | 32 | 49 | 33 | R157 | R95 | C61 | R166 | D8 | 46 | 45 | U9 | 19 | R147 | R146 | C117 | C119 | R96 | R99 | C120 | C121 | C116 | C118 | FB7 | C151 | C114 | C115 | C122 | FB8 | R98 | C123 | R100 | C124 | R97 | C109 | C110 | C112 | C113 | C107 | C108 | C111 | R22 | C28 | U15 | FB2 | U6 | FB3 | C64 | C77 | R14 | C24 | C30 | L3 | U7 | C135 | C136 | R103 | C14 | C8 | L2 | R108 | R156 | R159 | C126 | C133 | C132 | C131 | C13 | FB4 | C7 | L1 | R144 | R129 | R123 | R122 | R121 | R120 | U4 | C137 | C140 | C138 | C139 | C141 | R137 | R11 | C17 | 5 | R135 | C2 | R12 | R132 | R130 | C | E | G | J | L | N | R | 7 | 9 | PWR | TP4 | R8 | Q2 | Q1 | C18 | R3 | R4 | C11 | C37 | C55 | U16 | C29 | R50 | R24 | R23 | R25 | C32 | C165 | C31 | C57 | R29 | C33 | C27 | R81 | R80 | R84 | C93 | R45 | R48 | R82 | R46 | R47 | R165 | R83 | C168 | C166 | R85 | C167 | C157 | R86 | R87 | R88 | R89 | R90 | R91 | C169 | C156 | C160 | C163 | R92 | R93 | R94 | R75 | C173 | C153 | R52 | C35 | C171 | R53 | C76 | C149 | R148 | R149 | C150 | C148 | C147 | C146 | R70 | R69 | R68 | R67 | C145 | C144 | R66 | R65 | R64 | R63 | C172 | C155 | FB5 | C75 | R62 | C95 | C103 | R61 | R101 | R60 | C170 | C102 | R105 | R58 | C162 | R30 | R102 | C101 | R57 | C161 | C22 | R110 | R54 | R59 | R106 | C74 | C21 | R26 | R109 | R55 | C164 | C104 | R164 | R21 | R56 | C92 | R163 | C105 | C89 | C91 | C90 | C59 | R20 | R19 | R167 | R18 | C158 | R51 | C159 | 20 | R160 | C62 | R161 | C125 | C130 | C129 | R162 | R111 | R104 | C128 | C152 | C127 | R107 | C143 | C15 | R142 | R1 | R141 | R143 | R6 | C4 | C10 | C142 | R77 | C36 | R76 | R79 | R78 | C20 | R136 | DATE | DESIGN ENGR | PROJECT ENGR | ENGR MGR | NEXT ASSEMBLY | APPROVED | CHECKED | DRAFTING | ENGR | 1 OF 1 | USB | S1 | P1 | P5 | U13 | U2 | U14 | Y3 | U5 | J1 | Y1 | AM335x | C34 | U11 | U12 | RT1 | D7 | D6 | S2 | P3 | P8 | P9 | USB Host | HDMI | P6 | P10 | U8 | S/N | Y2 | P4 | S3 | 10/100 Ethernet | microSD Card | P2 | ASSEMBLY SOLDER SIDE
User.14: NONE
User.27: FIGURE | SIZE | 8.0 | 12.0 | 35.0 | 36.0 | 40.0 | 92.0 | 125.0 | 24.0 | 80.0 | 42.0x20.0 | DRILL CHART: TOP to BOTTOM | ALL UNITS ARE IN MILS | TOLERANCE | +3.0/-3.0 | +0.0/-0.0 | PLATED | NON-PLATED | QTY | 923 | 18 | 34 | 97 | 16 | 8 | 3 | 2 | 4
